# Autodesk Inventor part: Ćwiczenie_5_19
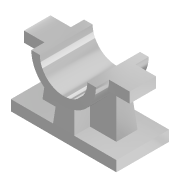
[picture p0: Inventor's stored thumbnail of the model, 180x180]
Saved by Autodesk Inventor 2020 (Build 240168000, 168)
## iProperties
Created: 2005-02
Part Number: Ćwiczenie_5_19
Document SubType Name: Modeling
Designer: F.Stasiak
Manufacturer: Standard
Standards Organization: Custom
Density: 2.7 g/cm^3
Material: Aluminium 6061
Appearance: Aluminium — polerowane
Manager: www.cadconsulting.pl
Company: Fabian Stasiak CAD Consulting
Author: F.Stasiak
Subject: Zbiór ćwiczeń. Autodesk Inventor 2020. Kurs podstawowy
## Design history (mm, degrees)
sketch "Szkic1"
  geometry: L1 (-50, 25)-(50, 25); L2 (50, 25)-(50, -25); L3 (50, -25)-(-50, -25); L4 (-50, -25)-(-50, 25); L5 (0, 25)-(0, -25); 2 further points
  constraints: 10 end point, 3 midpoint, 2 parallel, 1 coincident, 1 horizontal, 1 perpendicular
  dimensions: "d0" = 100 distance of L2.end L3.end; "d1" = 50 distance of L3.end L1.start
extrude "Wyciągnięcie proste1" new body sketch "Szkic1" distance "d2" = 10; taper "d3" = 0 deg
sketch "Szkic2"
  geometry: L1 (50, 25)-(50, -25) reference; L2 (-50, 25)-(50, 25) reference; L3 (-50, -25)-(-50, 25) reference; L4 (50, -25)-(-50, -25) reference; L5 (-35, 10)-(35, 10); L6 (35, 10)-(35, -10); L7 (35, -10)-(-35, -10); L8 (-35, -10)-(-35, 10)
  constraints: 8 end point, 3 other
  dimensions: "d4" = 20 distance of L5.end L6.end
extrude "Wyciągnięcie proste2" join sketch "Szkic2" distance "d5" = 50; taper "d6" = -5 deg
sketch "Szkic3"
  geometry: L1 (30.626, 60)-(-30.626, 60) reference; A1 r 30.626 centre (0, 60) between (-30.626, 60) and (30.626, 60)
  constraints: 2 end point, 2 point on circle, 1 centre point, 1 midpoint
extrude "Wyciągnięcie proste3" join sketch "Szkic3" stored distance "d7" = 50; taper "d8" = 0 deg
sketch "Szkic4"
  geometry: C1 r 22.5 at (0, 60); A1 r 30.626 centre (0, 60) between (-30.626, 60) and (30.626, 60) reference
  constraints: 1 centre point, 1 coincident
  dimensions: "d9" = 45 diameter of C1
extrude "Wyciągnięcie proste4" cut sketch "Szkic4" extent not by distance; stored distance "d10" = 10; taper "d11" = 0 deg
sketch "Szkic5"
  geometry: L1 (-50, 25)-(50, 25) reference; L2 (50, -25)-(-50, -25) reference; L3 (-10, 25)-(10, 25); L4 (10, 25)-(10, -25); L5 (10, -25)-(-10, -25); L6 (-10, -25)-(-10, 25); 2 further points
  constraints: 8 end point, 4 midpoint, 2 parallel, 1 horizontal, 1 perpendicular
  dimensions: "d13" = 20 distance between parallel lines of L4 L6
extrude "Wyciągnięcie proste5" join sketch "Szkic5" stored distance "d14" = 10; taper "d15" = -5 deg
sketch "Szkic9"
  geometry: L1 (-25, 60)-(25, 60) reference; L2 (12.5, 60)-(-12.5, 60); L3 (-12.5, 60)-(-12.5, 50); L4 (-12.5, 50)-(12.5, 50); L5 (12.5, 50)-(12.5, 60); 1 further point
  constraints: 8 end point, 2 midpoint, 2 parallel, 1 horizontal, 1 perpendicular
  dimensions: "d27" = 25 distance between parallel lines of L5 L3; "d28" = 10 distance of L4.end L2.start
extrude "Wyciągnięcie proste9" join sketch "Szkic9" stored distance "d29" = 10; taper "d30" = 0 deg
sketch "Szkic10"
  geometry: L1 (60, 37.5)-(50, 37.5) reference; L2 (60, 12.5)-(60, 37.5) reference; L3 (50, 12.5)-(60, 12.5) reference; L4 (50, 37.5)-(50, 12.5) reference
extrude "Wyciągnięcie proste10" join sketch "Szkic10" stored distance "d31" = 10; taper "d32" = 0 deg
node "Bryła1"
node "Korpusy bryłowe"
node "Korpusy powierzchniowe"
node "Pętla rzutowana1"
